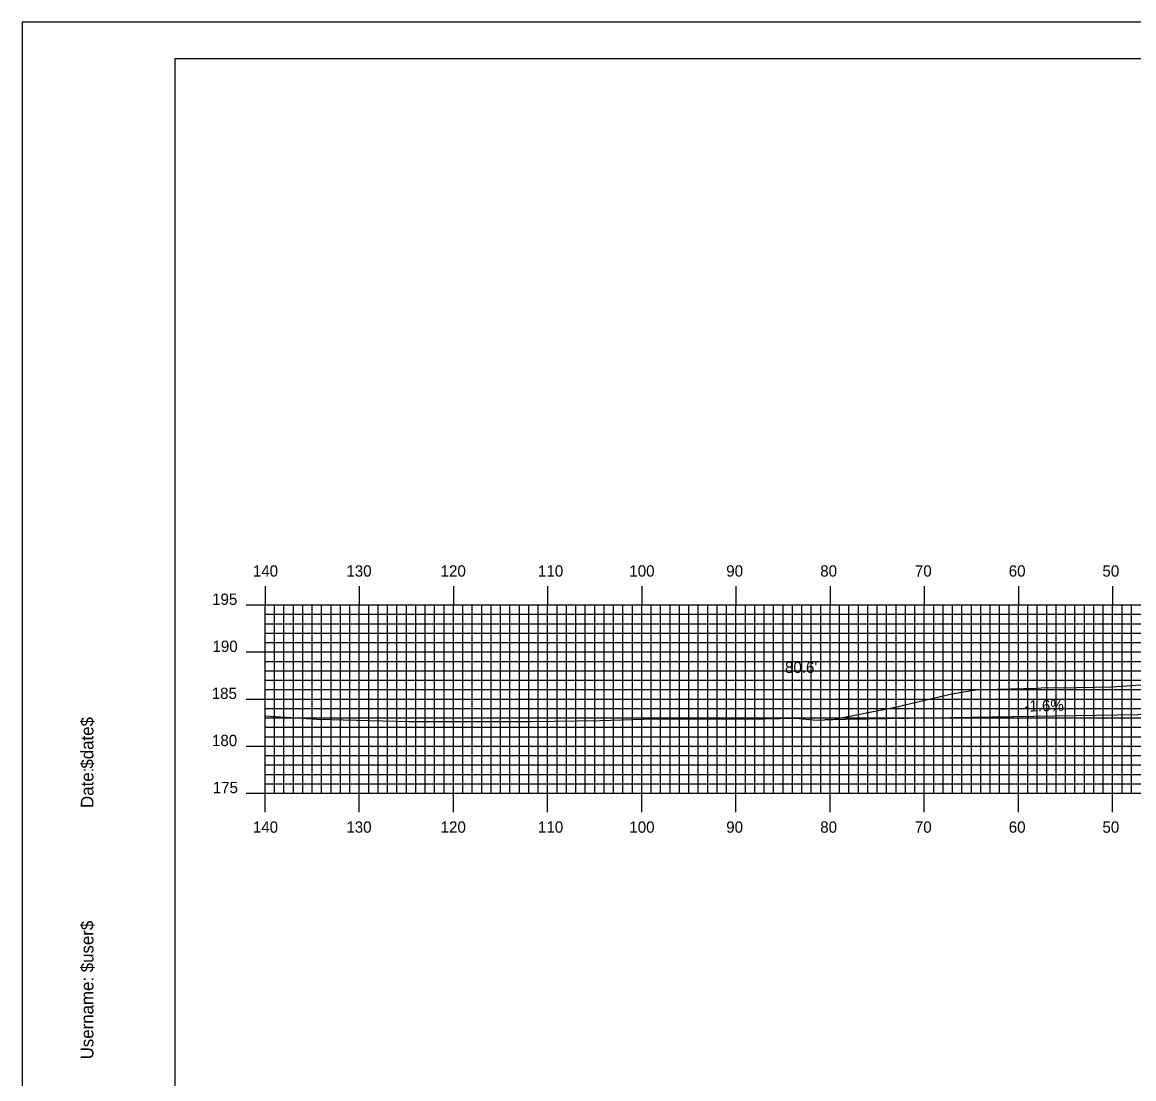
# Model space of a CAD drawing. Extents: x 1823179 to 1823522, y 442591 to 442811.
# Drawn here: x 1823179 to 1823297, y 442698.3 to 442810.5 of the extents above; entities that cross this region are included whole.
import ezdxf

# ---------------------------------------------------------------- set-up
doc = ezdxf.new("R2010")
doc.units = 0
for name, color, linetype in [('ANNOTATION', 7, 'Continuous'), ('BORDER', 7, 'Continuous'), ('D_Roadway_FinishedGrade', 7, 'Continuous'), ('D_Text_Standard', 7, 'Continuous'), ('H_V ANNOTATION', 7, 'Continuous'), ('MAJOR', 7, 'Continuous'), ('MINOR', 7, 'Continuous'), ('PLOT BOUNDARY', 7, 'Continuous'), ('S_Roadway_Centerline', 7, 'Continuous')]:
    doc.layers.add(name, color=color, linetype=linetype)

msp = doc.modelspace()

# ---------------------------------------------------------------- linework, layer by layer
at = {"layer": 'BORDER'}
msp.add_lwpolyline([(1823195.2, 442596.67), (1823515.2, 442596.67), (1823515.2, 442806.67), (1823195.2, 442806.67)], close=True, dxfattribs=at)
at = {"layer": 'D_Roadway_FinishedGrade'}
msp.add_line((1823310.62, 442737.2), (1823264.23, 442736.46), dxfattribs=at)
at = {"layer": 'MAJOR'}
for p, q in [((1823204.8, 442750.67), (1823204.8, 442748.67)), ((1823214.8, 442750.67), (1823214.8, 442748.67)), ((1823224.8, 442750.67), (1823224.8, 442748.67)), ((1823234.8, 442750.67), (1823234.8, 442748.67)), ((1823244.8, 442750.67), (1823244.8, 442748.67)), ((1823254.8, 442750.67), (1823254.8, 442748.67)), ((1823264.8, 442750.67), (1823264.8, 442748.67)), ((1823274.8, 442750.67), (1823274.8, 442748.67)), ((1823284.8, 442750.67), (1823284.8, 442748.67)), ((1823294.8, 442750.67), (1823294.8, 442748.67)), ((1823202.79, 442748.67), (1823204.8, 442748.67)), ((1823204.8, 442748.67), (1823484.8, 442748.67)), ((1823204.8, 442728.67), (1823204.8, 442748.67)), ((1823204.8, 442728.67), (1823204.8, 442748.67)), ((1823204.8, 442748.67), (1823484.8, 442748.67)), ((1823214.8, 442728.67), (1823214.8, 442748.67)), ((1823224.8, 442728.67), (1823224.8, 442748.67)), ((1823234.8, 442728.67), (1823234.8, 442748.67)), ((1823244.8, 442728.67), (1823244.8, 442748.67)), ((1823254.8, 442728.67), (1823254.8, 442748.67)), ((1823264.8, 442728.67), (1823264.8, 442748.67)), ((1823274.8, 442728.67), (1823274.8, 442748.67)), ((1823284.8, 442728.67), (1823284.8, 442748.67)), ((1823294.8, 442728.67), (1823294.8, 442748.67)), ((1823202.79, 442743.67), (1823204.8, 442743.67)), ((1823204.8, 442743.67), (1823484.8, 442743.67)), ((1823202.79, 442738.67), (1823204.8, 442738.67)), ((1823204.8, 442738.67), (1823484.8, 442738.67)), ((1823202.79, 442733.67), (1823204.8, 442733.67)), ((1823204.8, 442733.67), (1823484.8, 442733.67)), ((1823202.79, 442728.67), (1823204.8, 442728.67)), ((1823204.8, 442728.67), (1823484.8, 442728.67)), ((1823204.8, 442728.67), (1823484.8, 442728.67)), ((1823204.8, 442726.66), (1823204.8, 442728.67)), ((1823214.8, 442726.66), (1823214.8, 442728.67)), ((1823224.8, 442726.66), (1823224.8, 442728.67)), ((1823234.8, 442726.66), (1823234.8, 442728.67)), ((1823244.8, 442726.66), (1823244.8, 442728.67)), ((1823254.8, 442726.66), (1823254.8, 442728.67)), ((1823264.8, 442726.66), (1823264.8, 442728.67)), ((1823274.8, 442726.66), (1823274.8, 442728.67)), ((1823284.8, 442726.66), (1823284.8, 442728.67)), ((1823294.8, 442726.66), (1823294.8, 442728.67))]:
    msp.add_line(p, q, dxfattribs=at)
at = {"layer": 'MINOR'}
for p, q in [((1823205.8, 442728.67), (1823205.8, 442748.67)), ((1823206.8, 442728.67), (1823206.8, 442748.67)), ((1823207.8, 442728.67), (1823207.8, 442748.67)), ((1823208.8, 442728.67), (1823208.8, 442748.67)), ((1823209.8, 442728.67), (1823209.8, 442748.67)), ((1823210.8, 442728.67), (1823210.8, 442748.67)), ((1823211.8, 442728.67), (1823211.8, 442748.67)), ((1823212.8, 442728.67), (1823212.8, 442748.67)), ((1823213.8, 442728.67), (1823213.8, 442748.67)), ((1823215.8, 442728.67), (1823215.8, 442748.67)), ((1823216.8, 442728.67), (1823216.8, 442748.67)), ((1823217.8, 442728.67), (1823217.8, 442748.67)), ((1823218.8, 442728.67), (1823218.8, 442748.67)), ((1823219.8, 442728.67), (1823219.8, 442748.67)), ((1823220.8, 442728.67), (1823220.8, 442748.67)), ((1823221.8, 442728.67), (1823221.8, 442748.67)), ((1823222.8, 442728.67), (1823222.8, 442748.67)), ((1823223.8, 442728.67), (1823223.8, 442748.67)), ((1823225.8, 442728.67), (1823225.8, 442748.67)), ((1823226.8, 442728.67), (1823226.8, 442748.67)), ((1823227.8, 442728.67), (1823227.8, 442748.67)), ((1823228.8, 442728.67), (1823228.8, 442748.67)), ((1823229.8, 442728.67), (1823229.8, 442748.67)), ((1823230.8, 442728.67), (1823230.8, 442748.67)), ((1823231.8, 442728.67), (1823231.8, 442748.67)), ((1823232.8, 442728.67), (1823232.8, 442748.67)), ((1823233.8, 442728.67), (1823233.8, 442748.67)), ((1823235.8, 442728.67), (1823235.8, 442748.67)), ((1823236.8, 442728.67), (1823236.8, 442748.67)), ((1823237.8, 442728.67), (1823237.8, 442748.67)), ((1823238.8, 442728.67), (1823238.8, 442748.67)), ((1823239.8, 442728.67), (1823239.8, 442748.67)), ((1823240.8, 442728.67), (1823240.8, 442748.67)), ((1823241.8, 442728.67), (1823241.8, 442748.67)), ((1823242.8, 442728.67), (1823242.8, 442748.67)), ((1823243.8, 442728.67), (1823243.8, 442748.67)), ((1823245.8, 442728.67), (1823245.8, 442748.67)), ((1823246.8, 442728.67), (1823246.8, 442748.67)), ((1823247.8, 442728.67), (1823247.8, 442748.67)), ((1823248.8, 442728.67), (1823248.8, 442748.67)), ((1823249.8, 442728.67), (1823249.8, 442748.67)), ((1823250.8, 442728.67), (1823250.8, 442748.67)), ((1823251.8, 442728.67), (1823251.8, 442748.67)), ((1823252.8, 442728.67), (1823252.8, 442748.67)), ((1823253.8, 442728.67), (1823253.8, 442748.67)), ((1823255.8, 442728.67), (1823255.8, 442748.67)), ((1823256.8, 442728.67), (1823256.8, 442748.67)), ((1823257.8, 442728.67), (1823257.8, 442748.67)), ((1823258.8, 442728.67), (1823258.8, 442748.67)), ((1823259.8, 442728.67), (1823259.8, 442748.67)), ((1823260.8, 442728.67), (1823260.8, 442748.67)), ((1823261.8, 442728.67), (1823261.8, 442748.67)), ((1823262.8, 442728.67), (1823262.8, 442748.67)), ((1823263.8, 442728.67), (1823263.8, 442748.67)), ((1823265.8, 442728.67), (1823265.8, 442748.67)), ((1823266.8, 442728.67), (1823266.8, 442748.67)), ((1823267.8, 442728.67), (1823267.8, 442748.67)), ((1823268.8, 442728.67), (1823268.8, 442748.67)), ((1823269.8, 442728.67), (1823269.8, 442748.67)), ((1823270.8, 442728.67), (1823270.8, 442748.67)), ((1823271.8, 442728.67), (1823271.8, 442748.67)), ((1823272.8, 442728.67), (1823272.8, 442748.67)), ((1823273.8, 442728.67), (1823273.8, 442748.67)), ((1823275.8, 442728.67), (1823275.8, 442748.67)), ((1823276.8, 442728.67), (1823276.8, 442748.67)), ((1823277.8, 442728.67), (1823277.8, 442748.67)), ((1823278.8, 442728.67), (1823278.8, 442748.67)), ((1823279.8, 442728.67), (1823279.8, 442748.67)), ((1823280.8, 442728.67), (1823280.8, 442748.67)), ((1823281.8, 442728.67), (1823281.8, 442748.67)), ((1823282.8, 442728.67), (1823282.8, 442748.67)), ((1823283.8, 442728.67), (1823283.8, 442748.67)), ((1823285.8, 442728.67), (1823285.8, 442748.67)), ((1823286.8, 442728.67), (1823286.8, 442748.67)), ((1823287.8, 442728.67), (1823287.8, 442748.67)), ((1823288.8, 442728.67), (1823288.8, 442748.67)), ((1823289.8, 442728.67), (1823289.8, 442748.67)), ((1823290.8, 442728.67), (1823290.8, 442748.67)), ((1823291.8, 442728.67), (1823291.8, 442748.67)), ((1823292.8, 442728.67), (1823292.8, 442748.67)), ((1823293.8, 442728.67), (1823293.8, 442748.67)), ((1823295.8, 442728.67), (1823295.8, 442748.67)), ((1823296.8, 442728.67), (1823296.8, 442748.67)), ((1823204.8, 442747.67), (1823484.8, 442747.67)), ((1823204.8, 442747.67), (1823206.8, 442747.67)), ((1823204.8, 442746.67), (1823484.8, 442746.67)), ((1823204.8, 442746.67), (1823206.8, 442746.67)), ((1823204.8, 442745.67), (1823484.8, 442745.67)), ((1823204.8, 442745.67), (1823206.8, 442745.67)), ((1823204.8, 442744.67), (1823484.8, 442744.67)), ((1823204.8, 442744.67), (1823206.8, 442744.67)), ((1823204.8, 442742.67), (1823484.8, 442742.67)), ((1823204.8, 442742.67), (1823206.8, 442742.67)), ((1823204.8, 442741.67), (1823484.8, 442741.67)), ((1823204.8, 442741.67), (1823206.8, 442741.67)), ((1823204.8, 442740.67), (1823484.8, 442740.67)), ((1823204.8, 442740.67), (1823206.8, 442740.67)), ((1823204.8, 442739.67), (1823484.8, 442739.67)), ((1823204.8, 442739.67), (1823206.8, 442739.67)), ((1823204.8, 442737.67), (1823484.8, 442737.67)), ((1823204.8, 442737.67), (1823206.8, 442737.67)), ((1823204.8, 442736.67), (1823484.8, 442736.67)), ((1823204.8, 442736.67), (1823206.8, 442736.67)), ((1823204.8, 442735.67), (1823484.8, 442735.67)), ((1823204.8, 442735.67), (1823206.8, 442735.67)), ((1823204.8, 442734.67), (1823484.8, 442734.67)), ((1823204.8, 442734.67), (1823206.8, 442734.67)), ((1823204.8, 442732.67), (1823484.8, 442732.67)), ((1823204.8, 442732.67), (1823206.8, 442732.67)), ((1823204.8, 442731.67), (1823484.8, 442731.67)), ((1823204.8, 442731.67), (1823206.8, 442731.67)), ((1823204.8, 442730.67), (1823484.8, 442730.67)), ((1823204.8, 442730.67), (1823206.8, 442730.67)), ((1823204.8, 442729.67), (1823484.8, 442729.67)), ((1823204.8, 442729.67), (1823206.8, 442729.67))]:
    msp.add_line(p, q, dxfattribs=at)
at = {"layer": 'PLOT BOUNDARY'}
msp.add_lwpolyline([(1823179.01, 442590.55), (1823519.01, 442590.55), (1823519.01, 442810.55), (1823179.01, 442810.55)], close=True, dxfattribs=at)
at = {"layer": 'S_Roadway_Centerline'}
msp.add_lwpolyline([(1823204.8, 442736.89), (1823210.29, 442736.53), (1823220.1, 442736.27), (1823227.13, 442736.28), (1823233.07, 442736.29), (1823240.38, 442736.4), (1823246.08, 442736.56), (1823254.11, 442736.53), (1823257.76, 442736.55), (1823261.17, 442736.65), (1823263.36, 442736.42), (1823265.1, 442736.49), (1823271.72, 442737.81), (1823271.85, 442737.82), (1823272.59, 442738.03), (1823273.04, 442738.13), (1823277.73, 442739.23), (1823278.14, 442739.29), (1823280.47, 442739.67), (1823281.17, 442739.67), (1823286.78, 442739.83), (1823287.64, 442739.89), (1823289.11, 442739.86), (1823294.66, 442739.97), (1823298.87, 442740.23)], dxfattribs=at)

# ---------------------------------------------------------------- texts
at = {"layer": 'ANNOTATION'}
msp.add_text('-1.6%', height=1.2, rotation=0.9165, dxfattribs=at).set_placement((1823285.43, 442737.33))
at = {"layer": 'BORDER'}
for s, p in [('$date$', (1823186.57, 442731.28)), ('Date:', (1823186.57, 442727.1)), ('$user$', (1823186.57, 442709.65)), ('Username:', (1823186.57, 442700.4))]:
    msp.add_text(s, height=1.339, rotation=90, dxfattribs=at).set_placement(p)
at = {"layer": 'D_Text_Standard'}
msp.add_text("80.6'", height=1.2, dxfattribs=at).set_placement((1823260.01, 442741.43))
at = {"layer": 'H_V ANNOTATION'}
for s, p in [('140', (1823203.5, 442751.67)), ('130', (1823213.43, 442751.67)), ('120', (1823223.44, 442751.67)), ('110', (1823233.78, 442751.67)), ('100', (1823243.48, 442751.67)), ('90', (1823253.77, 442751.67)), ('80', (1823263.75, 442751.67)), ('70', (1823273.8, 442751.67)), ('60', (1823283.77, 442751.67)), ('50', (1823293.72, 442751.67)), ('195', (1823199.17, 442748.67)), ('190', (1823199.21, 442743.67)), ('185', (1823199.13, 442738.67)), ('180', (1823199.16, 442733.67)), ('175', (1823199.24, 442728.67)), ('140', (1823203.5, 442724.47)), ('130', (1823213.43, 442724.47)), ('120', (1823223.44, 442724.47)), ('110', (1823233.78, 442724.47)), ('100', (1823243.48, 442724.47)), ('90', (1823253.77, 442724.47)), ('80', (1823263.75, 442724.47)), ('70', (1823273.8, 442724.47)), ('60', (1823283.77, 442724.47)), ('50', (1823293.72, 442724.47))]:
    msp.add_text(s, height=1.2, dxfattribs=at).set_placement(p)
at = {"layer": 'MAJOR'}
msp.add_text('-', height=0.012, dxfattribs=at).set_placement((1823204.79, 442728.67))

doc.saveas('drawing.dxf')
